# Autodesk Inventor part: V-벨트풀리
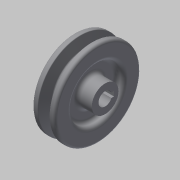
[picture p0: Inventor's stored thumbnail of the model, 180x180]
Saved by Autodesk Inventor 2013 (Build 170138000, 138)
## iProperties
Created: 2015-02
Part Number: V-벨트풀리
Material: 일반
Document SubType Name: Modeling
Designer: Administrator
Density: 1 g/cm^3
Author: Administrator
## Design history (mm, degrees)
sketch "스케치1"
  geometry: L1 (0, 0)-(25, 0); L2 (0, 0)-(0, 11); L3 (0, 11)-(6, 11); L4 (6, 11)-(6, 21.5); L5 (6, 21.5)-(0, 21.5); L6 (0, 21.5)-(0, 35.2); L7 (0, 35.2)-(4.675, 35.2); L8 (4.675, 35.2)-(7.426, 26.2); L9 (7.426, 26.2)-(11.574, 26.2); L10 (11.574, 26.2)-(14.325, 35.2); L11 (14.325, 35.2)-(19, 35.2); L12 (19, 35.2)-(19, 21.5); L13 (19, 21.5)-(13, 21.5); L14 (13, 21.5)-(13, 11); L15 (13, 11)-(25, 11); L16 (25, 11)-(25, 0); L17 (0, 32.5)-(19, 32.5); 3 further points
  constraints: 34 end point, 9 parallel, 6 equal length, 6 point on line, 3 perpendicular, 2 collinear, 1 horizontal, 1 midpoint, 1 vertical alignment
  dimensions: "d0" = 25 distance of L1.start L1.end; "d1" = 43 diameter of L5 L1; "d3" = 19 distance of L11.end L6.end; "d4" = 6 distance of L5.end L4.end; "d5" = 107 deg angle of L9 L8; "d6" = 65 diameter of L17 L1; "d7" = 6.3 distance between parallel lines of L9 L17; "d8" = 2.7 distance between parallel lines of L11 L17; "d9" = 22 diameter of L3 L1; "d10" = 8 distance of point (13.5, 32.5) point (5.5, 32.5)
revolve "회전1" sketch "스케치1" stored, may be unused: angle "d11" = 90 deg
sketch "스케치2"
  geometry: L1 (-2, 7.3)-(2, 7.3); L2 (-2, 7.3)-(-2, 5.123); L3 (2, 7.3)-(2, 5.123); C1 r 11 at (0, 0) reference; A1 r 5.5 centre (0, 0) between (-2, 5.123) and (2, 5.123); 1 further point
  constraints: 6 end point, 2 point on circle, 1 centre point, 1 coincident, 1 horizontal, 1 midpoint, 1 parallel, 1 perpendicular, 1 vertical alignment
  dimensions: "d12" = 11 diameter of A1; "d14" = 4 distance of L1.start L1.end; "d15" = 7.3 distance from line of C1.centre L1
extrude "돌출1" cut sketch "스케치2" stored distance "d16" = 10; taper "d17" = 0 deg
fillet "모깎기1" dims "d18" = 1
fillet "모깎기2" dims "d19" = 0.5
fillet "모깎기3" dims "d20" = 2
fillet "모깎기4" dims "d21" = 3
node "솔리드1"
